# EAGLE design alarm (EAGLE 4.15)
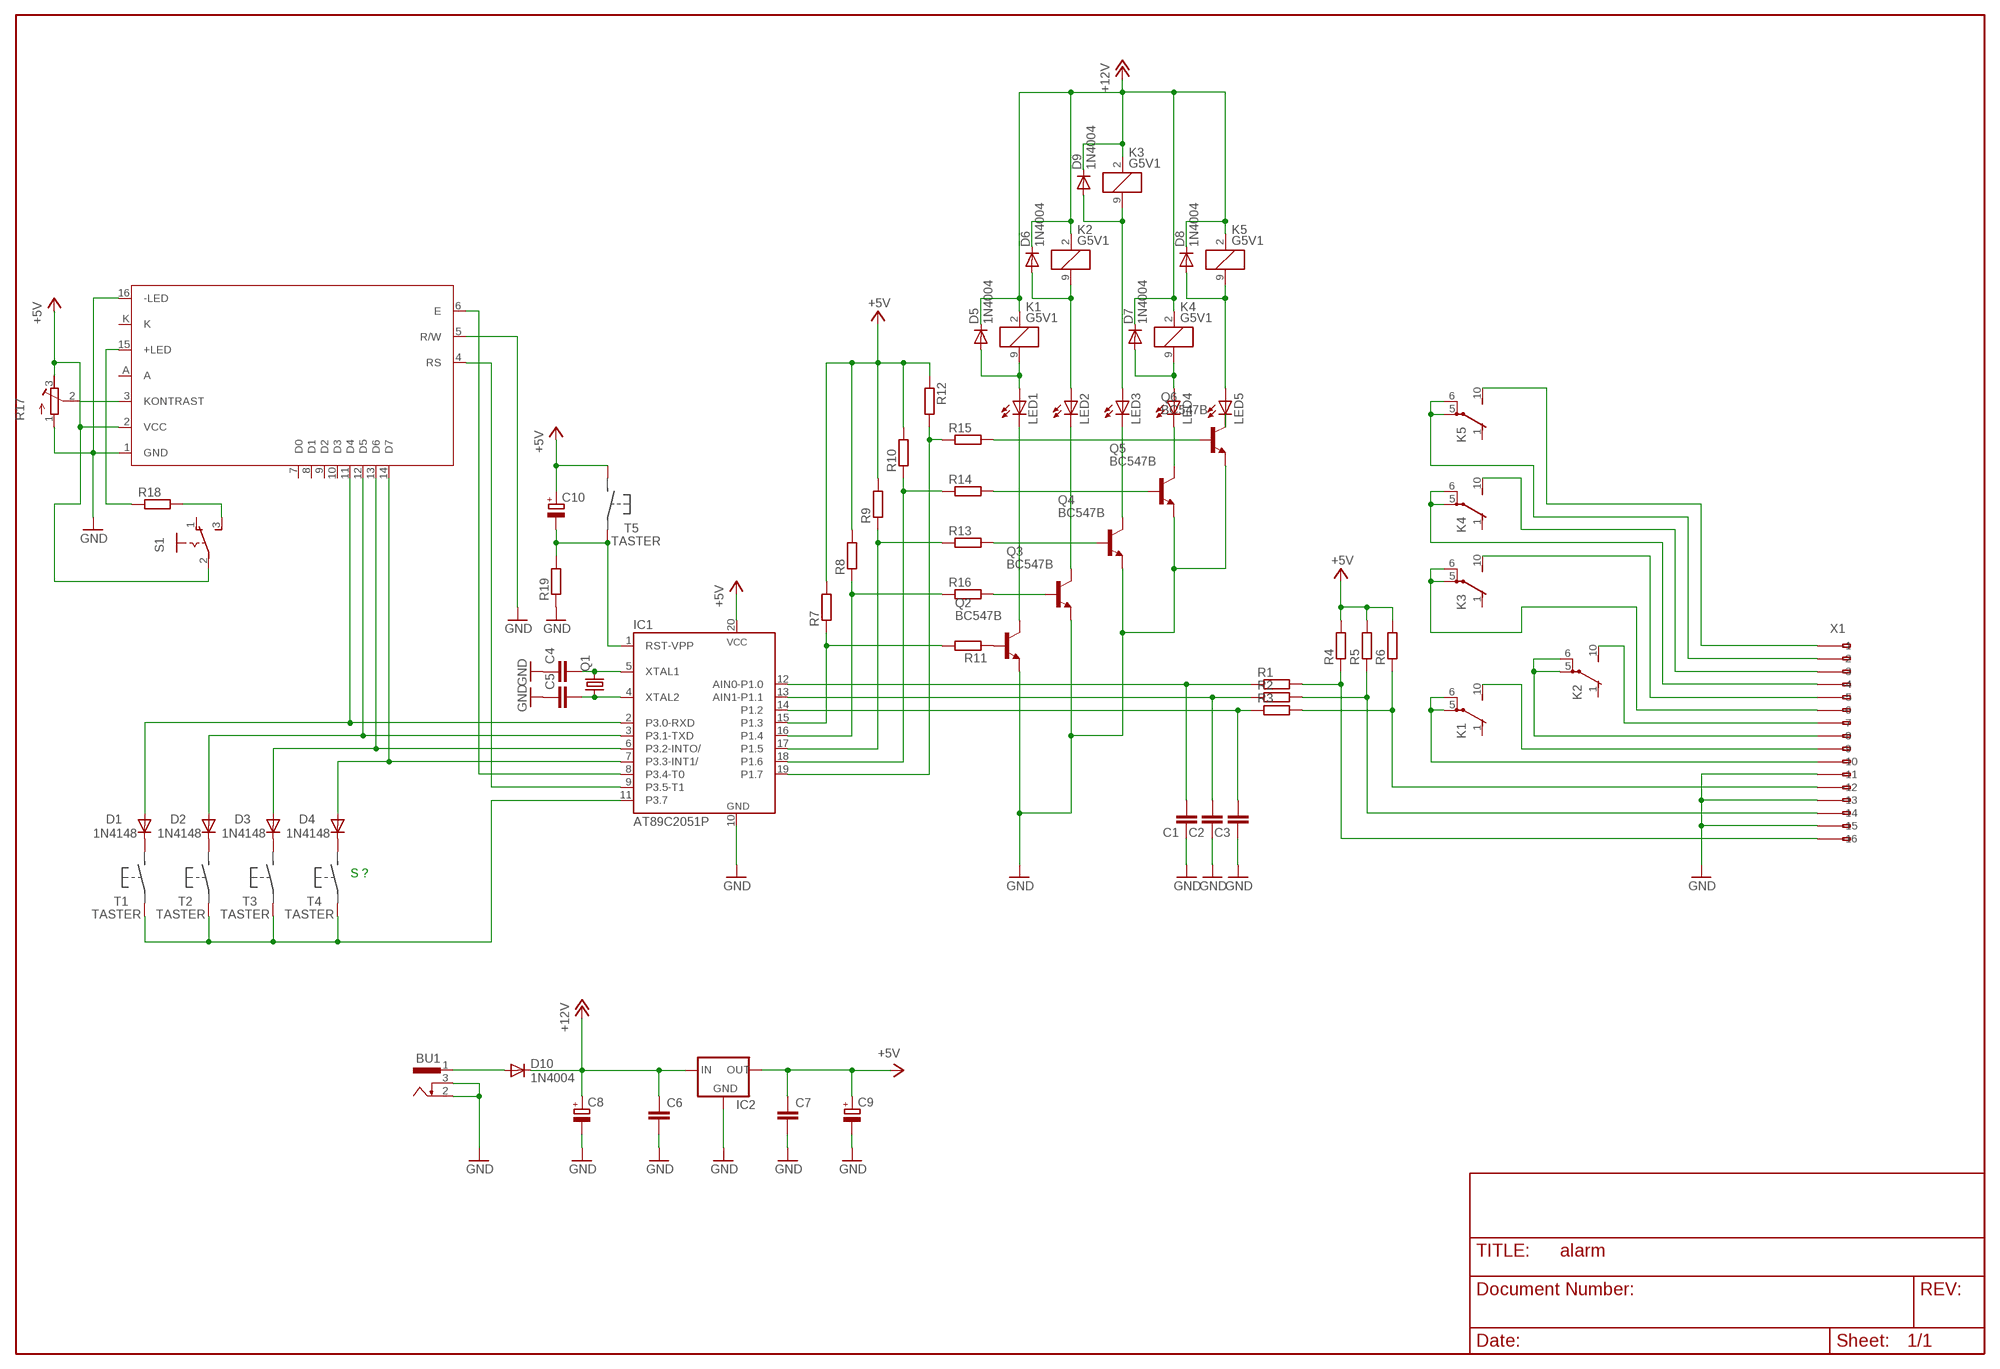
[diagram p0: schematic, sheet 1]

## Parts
BU1  733989-55  [733989-5]
C1  C-EU025-025X050  [C025-025X050]
C2  C-EU025-025X050  [C025-025X050]
C3  C-EU025-025X050  [C025-025X050]
C4  C-EU050-024X044  [C050-024X044]
C5  C-EU050-024X044  [C050-024X044]
C6  C-EU050-025X075  [C050-025X075]
C7  C-EU050-025X075  [C050-025X075]
C8  CPOL-EUE3.5-10  [E3,5-10]
C9  CPOL-EUE2-5  [E2-5]
C10  CPOL-EUE2.5-5  [E2,5-5]
D1  1N4148  [DO35-10]
D2  1N4148  [DO35-10]
D3  1N4148  [DO35-10]
D4  1N4148  [DO35-10]
D5  1N4004  [DO41-10]
D6  1N4004  [DO41-10]
D7  1N4004  [DO41-10]
D8  1N4004  [DO41-10]
D9  1N4004  [DO41-10]
D10  1N4004  [DO41-10]
IC1  AT89C2051P  [DIL20]
IC2  78XXL  [78XXL]
K1  G5V1  [G5V1]
K2  G5V1  [G5V1]
K3  G5V1  [G5V1]
K4  G5V1  [G5V1]
K5  G5V1  [G5V1]
LCD1  LCD-DOT  [LCD-DOT]
LED1  LED5MM  [LED5MM]
LED2  LED5MM  [LED5MM]
LED3  LED5MM  [LED5MM]
LED4  LED5MM  [LED5MM]
LED5  LED5MM  [LED5MM]
Q1  CRYTALHC49U-V  [HC49U-V]
Q2  BC547B  [TO92]
Q3  BC547B  [TO92]
Q4  BC547B  [TO92]
Q5  BC547B  [TO92]
Q6  BC547B  [TO92]
R1  R-EU_0207/10  [0207/10]
R2  R-EU_0207/10  [0207/10]
R3  R-EU_0207/10  [0207/10]
R4  R-EU_0207/10  [0207/10]
R5  R-EU_0207/10  [0207/10]
R6  R-EU_0207/10  [0207/10]
R7  R-EU_0207/10  [0207/10]
R8  R-EU_0207/10  [0207/10]
R9  R-EU_0207/10  [0207/10]
R10  R-EU_0207/10  [0207/10]
R11  R-EU_0207/10  [0207/10]
R12  R-EU_0207/10  [0207/10]
R13  R-EU_0207/10  [0207/10]
R14  R-EU_0207/10  [0207/10]
R15  R-EU_0207/10  [0207/10]
R16  R-EU_0207/10  [0207/10]
R17  R-TRIMM64W  [RTRIM64W]
R18  R-EU_0309/10  [0309/10]
R19  R-EU_0207/10  [0207/10]
S1  255SB  [255SB]
T1  TASTER  [B3F-10XX]
T2  TASTER  [B3F-10XX]
T3  TASTER  [B3F-10XX]
T4  TASTER  [B3F-10XX]
T5  TASTER  [B3F-10XX]
X1  233-216  [233-216]

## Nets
+5V: C7.1 C9.+ C10.+ IC1.20(VCC) IC2.OUT LCD1.2(VCC) R4.2 R5.2 R6.2 R7.2 R8.2 R9.2 R10.2 R12.1 R17.3(A) S1.2(P) T5.1
+12V: C6.1 C8.+ D5.C D6.C D7.C D8.C D9.C D10.C IC2.IN K1.2 K2.2 K3.2 K4.2 K5.2
GND: BU1.2 BU1.3 C1.1 C2.1 C3.1 C4.1 C5.1 C6.2 C7.2 C8.- C9.- IC1.10(GND) IC2.GND LCD1.1(GND) LCD1.5(R/W) LCD1.16(-LED) Q2.1(E) Q3.1(E) Q4.1(E) Q5.1(E) Q6.1(E) R17.1(E) R19.1 X1.A11(-11) X1.A13(-13) X1.A15(-15)
N$1: C1.2 IC1.12(AIN0-P1.0) R1.1
N$2: C2.2 IC1.13(AIN1-P1.1) R2.1
N$3: C3.2 IC1.14(P1.2) R3.1
N$4: R1.2 R4.1 X1.A16(-16)
N$5: R2.2 R5.1 X1.A14(-14)
N$6: R3.2 R6.1 X1.A12(-12)
N$7: D1.A IC1.2(P3.0-RXD) LCD1.11(D4)
N$8: D2.A IC1.3(P3.1-TXD) LCD1.12(D5)
N$9: D3.A IC1.6(P3.2-INTO/) LCD1.13(D6)
N$10: D4.A IC1.7(P3.3-INT1/) LCD1.14(D7)
N$11: IC1.8(P3.4-T0) LCD1.6(E)
N$12: IC1.9(P3.5-T1) LCD1.4(RS)
N$13: C4.2 IC1.5(XTAL1) Q1.2
N$14: C5.2 IC1.4(XTAL2) Q1.1
N$15: IC1.11(P3.7) T1.3 T2.3 T3.3 T4.3
N$16: Q2.2(B) R11.1
N$17: D1.C T1.1
N$18: D2.C T2.1
N$19: D3.C T3.1
N$20: D4.C T4.1
N$21: Q3.2(B) R16.2
N$22: Q4.2(B) R13.2
N$23: Q5.2(B) R14.2
N$24: Q6.2(B) R15.2
N$25: IC1.19(P1.7) R12.2 R15.1
N$26: IC1.18(P1.6) R10.1 R14.1
N$27: IC1.17(P1.5) R9.1 R13.1
N$28: IC1.16(P1.4) R8.1 R16.1
N$29: IC1.15(P1.3) R7.1 R11.2
N$30: BU1.1 D10.A
N$31: C10.- IC1.1(RST-VPP) R19.2 T5.3
N$32: LED2.K(C) Q3.3(C)
N$33: D9.A K3.9 LED3.A
N$34: D5.A K1.9 LED1.A
N$35: D6.A K2.9 LED2.A
N$36: LED3.K(C) Q4.3(C)
N$37: D7.A K4.9 LED4.A
N$38: D8.A K5.9 LED5.A
N$39: LED1.K(C) Q2.3(C)
N$40: LED5.K(C) Q6.3(C)
N$41: LED4.K(C) Q5.3(C)
N$42: LCD1.15(+LED) R18.1
N$43: K1.5(2:P) K1.6(2:P) X1.A10(-10)
N$44: K1.10(2:S) X1.A9(-9)
N$48: K2.5(2:P) K2.6(2:P) X1.A8(-8)
N$49: K2.10(2:S) X1.A7(-7)
N$50: K3.5(2:P) K3.6(2:P) X1.A6(-6)
N$51: K3.10(2:S) X1.A5(-5)
N$52: K4.5(2:P) K4.6(2:P) X1.A4(-4)
N$53: K4.10(2:S) X1.A3(-3)
N$54: K5.5(2:P) K5.6(2:P) X1.A2(-2)
N$55: K5.10(2:S) X1.A1(-1)
N$56: LCD1.3(KONTRAST) R17.2(S)
N$60: R18.2 S1.3(S)
Unconnected: K1.1(2:O) K2.1(2:O) K3.1(2:O) K4.1(2:O) K5.1(2:O) LCD1.7(D0) LCD1.8(D1) LCD1.9(D2) LCD1.10(D3) LCD1.A LCD1.K S1.1(O) X1.B1(B-1) X1.B2(B-2) X1.B3(B-3) X1.B4(B-4) X1.B5(B-5) X1.B6(B-6) X1.B7(B-7) X1.B8(B-8) X1.B9(B-9) X1.B10(B-10) X1.B11(B-11) X1.B12(B-12) X1.B13(B-13) X1.B14(B-14) X1.B15(B-15) X1.B16(B-16)

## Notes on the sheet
- S ?

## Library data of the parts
BU1 = con-conrad:733989-55: FEMALE PRINT CONNECTOR Außen-Ø 4,2 mm, Innen 1.1 mm FUK HING Industries, distributor Conrad
C1-C7 = rcl:C-EU: CAPACITOR, European symbol
C8-C10 = rcl:CPOL-EU: POLARIZED CAPACITOR, European symbol
D1-D4 = diode:1N4148: DIODE
D5-D10 = diode:1N4004: DIODE
IC1 = atmel:AT89C2051: 80C31 MICROCONTROLLER 2 Kbytes FLASH 2.7 V
IC2 = v-reg:78XXL: VOLTAGE REGULATOR
K1-K5 = relay:G5V1: RELAY 1 x switch, 0.5 A/125 V AC, 1 A/24 V DC , Omron
LCD1 = display-lcd:LCD-DOT
LED1-LED5 = led:LED: LED
Q1 = crystal:CRYTAL: CRYSTAL
Q2-Q6 = transistor-npn:BC547*: NPN Transistor
R1-R16 R18 R19 = rcl:R-EU_: RESISTOR, European symbol
R17 = rcl:R-TRIMM: Trimm resistor
S1 = switch:255SB: SLIDING SWITCH distributor Buerklin, 11G810
T1-T5 = switch-omron:TASTER: Digi-Taster
X1 = con-wago255:233-216: WAGO

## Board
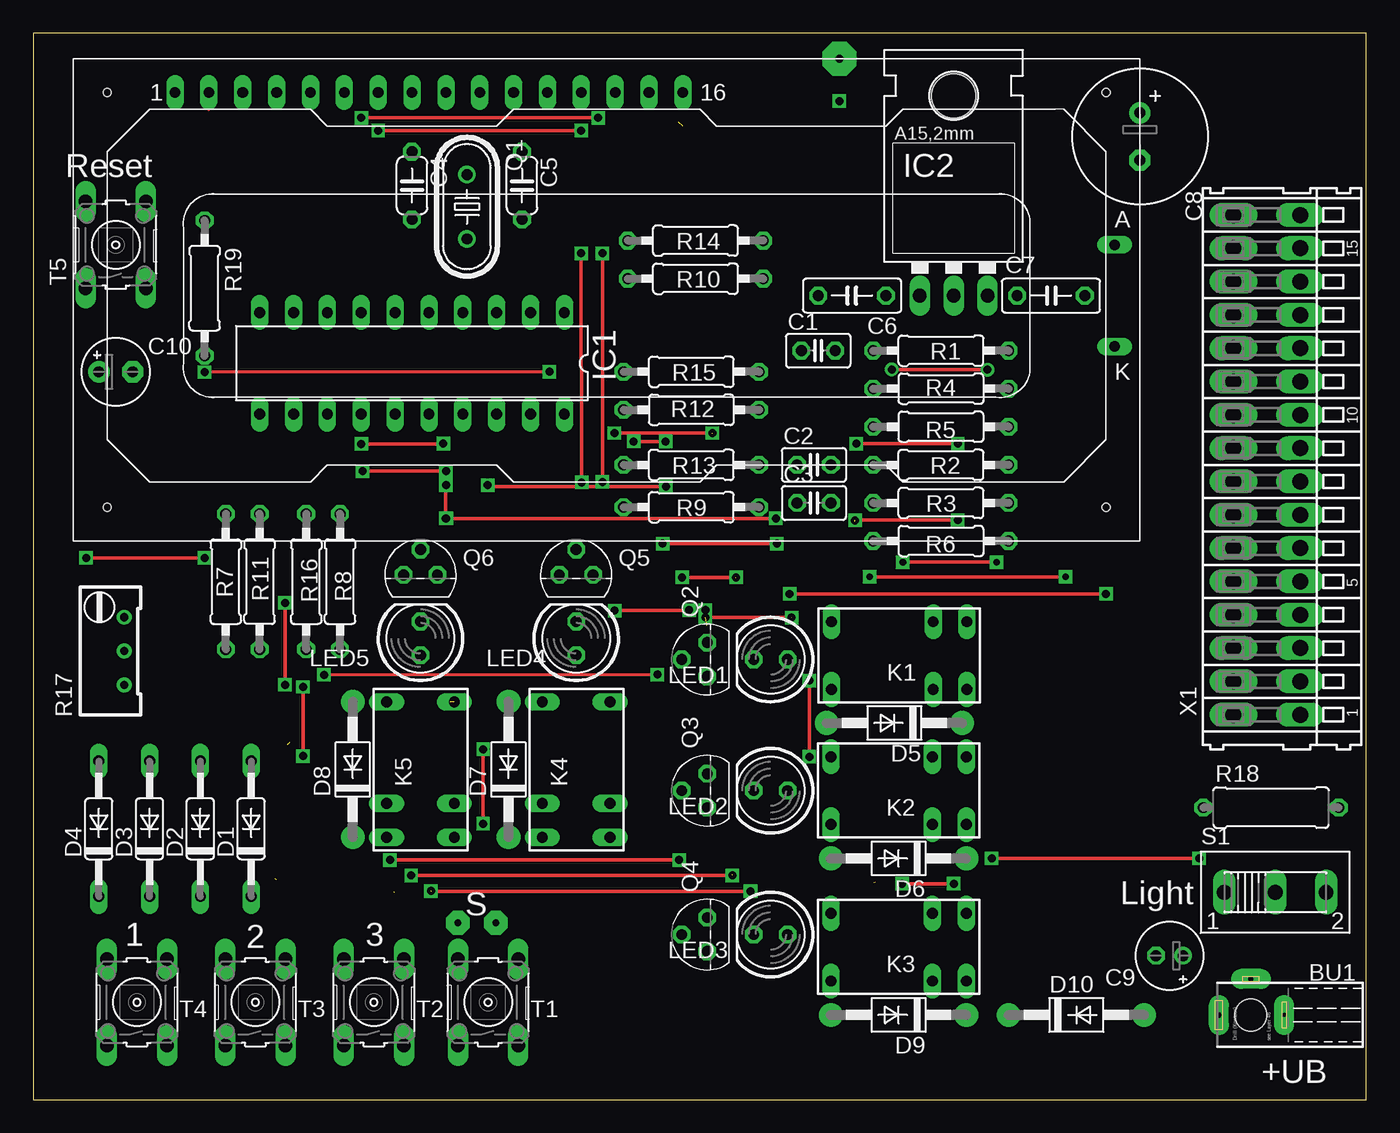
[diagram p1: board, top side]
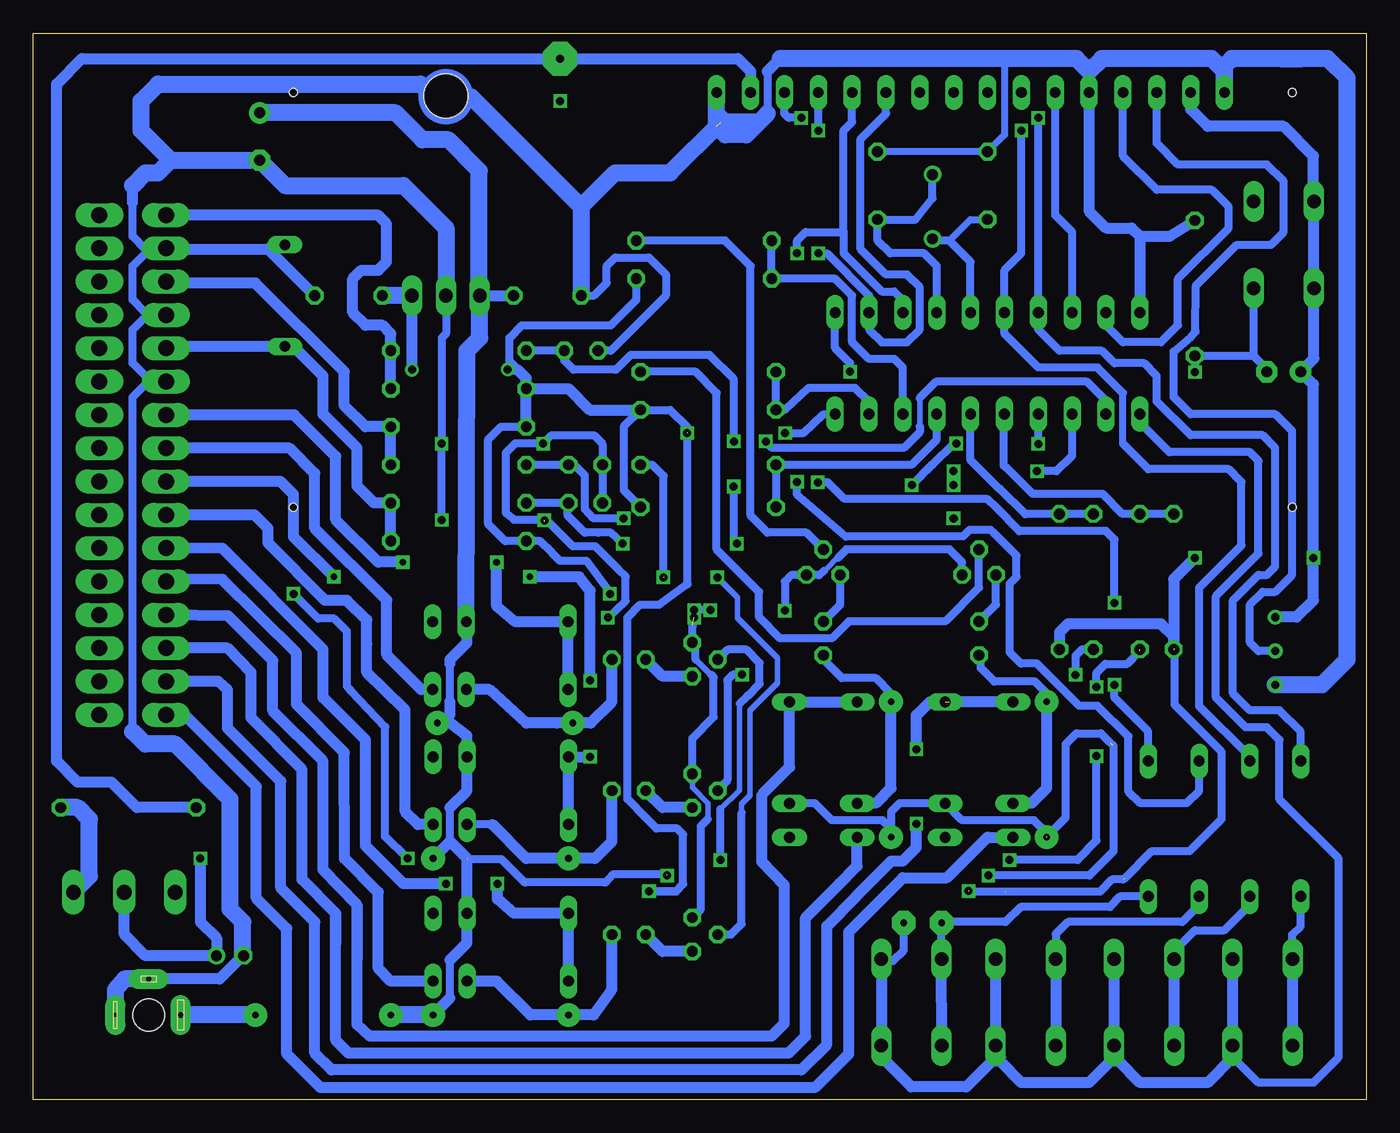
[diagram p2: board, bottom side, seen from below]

Size 100 x 80 mm. Coordinates in mm from the lower left corner, seen from the top.
Outline: 0,0 100,0 100,80 0,80 0,0
Copper layers (1*16): Top 0.035mm / dielectric 1.5mm / Bottom 0.035mm
Design rules "default": minimum track width 10mil, minimum drill 24mil, track to track 8mil, track to pad 8mil, pad to pad 8mil, via to via 8mil, smd to smd 8mil, copper to edge 40mil, drill to drill 8mil, minimum pad ring 10mil, minimum via ring 8mil, stop-mask expansion 4mil, vias tented up to drill 0mil, thermal gap 10mil

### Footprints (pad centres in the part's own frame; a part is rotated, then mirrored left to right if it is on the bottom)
733989-5 = drill 0.4 pad 1.5 long: 1 0,5.82; 3 2.7,3.42 | drill 0.3 pad 1.5 long: 2 0,0.92 | hole 2.4: 0,3.42
C025-025X050 = drill 0.813 octagon: 1 -1.27,0; 2 1.27,0
C050-024X044 = drill 0.813 octagon: 1 -2.54,0; 2 2.54,0
C050-025X075 = drill 0.813 octagon: 1 -2.54,0; 2 2.54,0
E3,5-10 = drill 0.813 pad 1.6 round: + -1.778,0 | drill 0.813 pad 1.6 octagon: - 1.778,0
E2-5 = drill 0.813 pad 1.27 round: + -1.016,0 | drill 0.813 pad 1.27 octagon: - 1.016,0
E2,5-5 = drill 0.813 pad 1.6 round: + -1.27,0 | drill 0.813 pad 1.6 octagon: - 1.27,0
DO35-10 = drill 0.813 long: A 5.08,0; C -5.08,0
DO41-10 = drill 0.5 pad 1.778 round: A 5.08,0; C -5.08,0
DIL20 = drill 0.813 long: 1 -11.43,-3.81; 2 -8.89,-3.81; 3 -6.35,-3.81; 4 -3.81,-3.81; 5 -1.27,-3.81; 6 1.27,-3.81; 7 3.81,-3.81; 8 6.35,-3.81; 9 8.89,-3.81; 10 11.43,-3.81; 11 11.43,3.81; 12 8.89,3.81; 13 6.35,3.81; 14 3.81,3.81; 15 1.27,3.81; 16 -1.27,3.81; 17 -3.81,3.81; 18 -6.35,3.81; 19 -8.89,3.81; 20 -11.43,3.81
78XXL = drill 1.016 long: GND 0,-3.81; IN -2.54,-3.81; OUT 2.54,-3.81 | hole 3.302: 0,11.176
G5V1 = drill 0.813 long: 1 -5.08,-2.54; 2 -2.54,-2.54; 5 5.08,-2.54; 6 5.08,2.54; 9 -2.54,2.54; 10 -5.08,2.54
LCD-DOT = drill 0.8 long: 1 -33.02,15.24; 2 -30.48,15.24; 3 -27.94,15.24; 4 -25.4,15.24; 5 -22.86,15.24; 6 -20.32,15.24; 7 -17.78,15.24; 8 -15.24,15.24; 9 -12.7,15.24; 10 -10.16,15.24; 11 -7.62,15.24; 12 -5.08,15.24; 13 -2.54,15.24; 14 0,15.24; 15 2.54,15.24; 16 5.08,15.24; A 37.465,3.81; K 37.465,-3.81 | hole 0.6: -38.1,15.24; 36.83,15.24; -38.1,-15.875; 36.83,-15.875
LED5MM = drill 0.813 octagon: A -1.27,0; K 1.27,0
HC49U-V = drill 0.813 round: 1 -2.413,0; 2 2.413,0
TO92 = drill 0.813 octagon: 1 1.27,0; 2 0,1.905; 3 -1.27,0
0207/10 = drill 0.813 octagon: 1 -5.08,0; 2 5.08,0
RTRIM64W = drill 0.61 round: 1 1.27,-2.54; 2 1.27,0; 3 1.27,2.54
0309/10 = drill 0.813 octagon: 1 -5.08,0; 2 5.08,0
255SB = drill 1.118 long: 1 -3.81,0; 2 0,0; 3 3.81,0
B3F-10XX = drill 1.016 long: 1 -3.251,2.261; 2 3.251,2.261; 3 -3.251,-2.261; 4 3.251,-2.261
233-216 = drill 1.2 long: A1 -18.75,2.5; A2 -16.25,2.5; A3 -13.75,2.5; A4 -11.25,2.5; A5 -8.75,2.5; A6 -6.25,2.5; A7 -3.75,2.5; A8 -1.25,2.5; A9 1.25,2.5; A10 3.75,2.5; A11 6.25,2.5; A12 8.75,2.5; A13 11.25,2.5; A14 13.75,2.5; A15 16.25,2.5; A16 18.75,2.5; B1 -18.75,-2.5; B2 -16.25,-2.5; B3 -13.75,-2.5; B4 -11.25,-2.5; B5 -8.75,-2.5; B6 -6.25,-2.5; B7 -3.75,-2.5; B8 -1.25,-2.5; B9 1.25,-2.5; B10 3.75,-2.5; B11 6.25,-2.5; B12 8.75,-2.5; B13 11.25,-2.5; B14 13.75,-2.5; B15 16.25,-2.5; B16 18.75,-2.5

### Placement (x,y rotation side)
BU1  94.77,6.34 90 top
C1  58.89,56.19 0 top
C2  58.57,47.62 0 top
C3  58.57,44.76 0 top
C4  28.41,68.57 270 top
C5  36.66,68.57 270 top
C6  61.43,60.32 180 top
C7  76.35,60.32 0 top
C8  83.02,72.26 270 top
C9  85.24,10.79 180 top
C10  6.18,54.61 0 top
D1  16.34,20.31 90 top
D2  12.54,20.31 90 top
D3  8.73,20.31 90 top
D4  4.92,20.31 90 top
D5  64.61,28.25 180 top
D6  64.92,18.09 180 top
D7  35.65,24.76 90 top
D8  23.96,24.76 90 top
D9  64.92,6.34 180 top
D10  78.26,6.34 0 top
IC1  28.41,55.24 180 top
IC2  69.05,64.13 0 top
K1  64.97,33.31 180 top
K2  64.92,23.17 180 top
K3  64.92,11.43 180 top
K4  40.73,24.76 90 top
K5  29.04,24.76 90 top
LCD1  43.65,60.32 0 top
LED1  55.32,33.02 180 top
LED2  55.32,23.17 180 top
LED3  55.32,12.38 180 top
LED4  40.73,34.6 90 top
LED5  29.04,34.6 90 top
Q1  32.54,66.99 270 top
Q2  50.56,33.02 90 top
Q3  50.56,23.17 90 top
Q4  50.56,12.38 90 top
Q5  40.73,39.37 0 top
Q6  29.04,39.37 0 top
R1  68.1,56.19 0 top
R2  68.1,47.62 0 top
R3  68.1,44.76 0 top
R4  68.1,53.34 180 top
R5  68.1,50.48 180 top
R6  68.1,41.91 180 top
R7  14.44,38.86 270 top
R8  23.01,38.86 270 top
R9  49.37,44.45 0 top
R10  49.68,61.59 0 top
R11  16.98,38.86 90 top
R12  49.37,51.75 180 top
R13  49.37,47.62 0 top
R14  49.68,64.45 0 top
R15  49.37,54.61 0 top
R16  20.47,38.86 270 top
R17  5.55,33.65 0 top
R18  92.86,21.9 0 top
R19  12.85,60.88 270 top
S1  93.18,15.55 0 top
T1  34.12,7.3 90 top
T2  25.55,7.3 90 top
T3  16.66,7.3 90 top
T4  7.77,7.3 90 top
T5  6.18,64.13 90 top
X1  92.55,47.62 90 top

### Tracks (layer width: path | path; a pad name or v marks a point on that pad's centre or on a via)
+5V  (via drill 0.6, 0.6 pad 1.02)  (6 unrouted)
  Top 0.254: v64.4,54.78 v71.6,54.75 | v3.96,40.64 v12.85,40.64 | v50.95,50.01 v43.6,50.01 | v71.91,18.09 v87.47,18.09 | C7.1 74.13,60.32 | LCD1.2 13.17,74.29 | R10.2 55.08,61.59 | v80.48,37.94 v56.74,37.94 | 29.84,15.63 v53.8,15.63
  Bottom 0.61: R5.2 64.92,50.48 65.88,49.53 65.88,43.18 64.61,41.91 R6.2 63.02,41.94 | 63.02,54.13 64.29,55.4 64.29,57.15 63.34,58.1 56.67,58.1 54.76,60 R10.2 | R9.2 55.71,45.72 55.71,50.48 R12.1 52.22,51.75 50.95,50.48 v50.95,50.01 | IC1.20 40.72,51.43 42.2,50.02 43.16,50.02 v43.6,50.01 | v71.91,18.09 73.61,19.73 73.6,27.96 76.16,30.65 | 76.16,30.65 76.21,30.75 | 76.16,30.65 76.47,31.01 76.47,35.12 77.43,36.09 78.63,36.09 v80.48,37.94 | 63.02,41.94 63.03,41.96 | 63.02,41.94 62.98,41.91 61.96,41.91 61.1,41.04 61.1,41.02 60.49,40.41 60.49,40.46 60.44,40.41 58.51,40.41 56.76,38.1 v56.74,37.94 | 50.91,50.01 50.91,38.68 53.02,37.13 54.47,37.13 55.44,36.16 55.44,22.55 53.99,21.1 53.99,21.08 53.25,20.34 51.7,20.34 51.24,19.88 51.24,16.18 | 51.24,16.18 51.77,15.62 v53.82,15.62 | 27.09,15.59 29.43,15.59 v29.82,15.64 | 27.01,15.59 19.98,15.59 19.06,16.5 18.22,16.5 | 14.36,33.83 14.36,29.61 10.83,26.08 10.83,21.05 13.25,18.64 16.07,18.64 18.1,16.61 | 51.24,16.18 51.79,15.63 v53.8,15.63
  Bottom 0.813: LCD1.2 13.17,74.29 11.9,73.02 6.18,73.02 3.96,70.8 3.96,67.62 3.92,67.58 T5.1 3.92,55.6 C10.+ 3.96,53.65 v3.96,40.64 3.96,37.46 5.23,36.19 R17.3 | R5.2 R4.2 | IC2.OUT 71.59,56.51 v71.6,54.75 | v64.4,54.78 63.65,54.76 63.02,54.13 R4.2 | S1.2 93.18,12.38 91.59,10.79 C9.+ 86.26,12.12 87.47,13.33 v87.47,18.09 | R12.1 58.25,51.75 59.84,53.34 R4.2 | R8.2 23.01,35.05 22.38,35.68 15.39,35.68 14.44,34.73 R7.2 14.44,39.05 v12.85,40.64
  Bottom 1.27: IC2.OUT C7.1
+12V  (via drill 0.6)  (5 unrouted)
  Top 0.254: K4.2 43.9,22.22 | D6.C 70.32,18.41 | v28.35,16.81 v52.44,16.81 52.59,16.71
  Bottom 0.61: 68.73,19.36 68.73,21.9 | 68.73,7.62 68.73,10.47 | 68.73,29.84 68.73,32.7 | D8.C 23.96,20 24.92,20.95 30.31,20.95 K5.2 35.01,22.22 35.65,21.58 35.65,20.31 | 35.65,20.31 D7.C | K4.2 41.36,22.22 40.09,20.95 36.28,20.95 35.65,20.31 | 63.08,16.28 57.09,16.28 56.53,16.89 52.44,16.89 | 67.45,18.03 64.88,18.03 63.18,16.33 | 19.04,26.61 18.94,26.51 18.94,18.64 20.77,16.81 v28.35,16.81 | 23.94,19.78 23.94,19.76 22.54,21.15 22.54,26.66 21.73,27.48 19.9,27.48 19.21,26.79
  Bottom 0.813: D6.C 68.73,19.36 67.46,18.09 K3.2 67.46,11.74 68.73,10.47 | 68.73,21.9 67.46,23.17 K2.2 67.46,27.3 68.73,28.25 D5.C 69.05,28.57 68.73,28.89 68.73,29.84 | 68.73,7.62 D9.C | 68.73,32.7 68.73,33.02 67.46,34.29 K1.2 | 66.54,60.32 IC2.IN C6.1
  Bottom 1.27: K1.2 67.46,56.19 66.51,57.15 IC2.IN | D9.C D10.C | C8.+ 72.83,74.04 70.8,72 68.86,72 66.54,69.69 66.54,60.32
GND  (via drill 0.6, 0.6 pad 1.02)  (6 unrouted)
  Top 0.254: C9.- 84.29,10.79 | v69.37,49.21 v61.75,49.21 | 61.66,43.48 v69.36,43.48 | v43.61,36.69 49.16,36.69 v49.2,36.72 | v50.42,36.72 v50.42,36.15 56.6,36.15 v56.9,36.16
  Bottom 0.254: C9.- 84.29,10.79 | 27.14,78.1 27.14,77.78 | v56.9,36.16 55.69,37.36
  Bottom 0.406: 39.61,40.66 39.66,40.66 40.5,39.82 40.68,39.67 | 41.03,39.34 40.91,39.47 41.09,39.34 | 42.05,39.34 42.02,39.37 Q5.1 | Q3.1 50.56,23.41 49.37,22.22 49.37,21.08 49.39,21.05 | 49.14,31.87 49.16,31.87 50.3,33.02
  Bottom 0.508: 27.14,77.78 27.14,72.38 C4.1 C5.1
  Bottom 0.61: 44.92,77.15 44.92,73.97 | 92.55,67.3 92.55,64.77 91.59,63.81 90,63.81 | 90,63.81 90.05,63.85 X1.A15 | 90,63.81 91.28,63.81 92.55,62.54 92.55,60 91.59,59.05 90.32,59.05 90.14,58.87 X1.A13 91.45,58.87 92.55,57.78 92.55,55.24 91.28,53.97 | X1.A11 90.05,53.93 90,53.97 91.28,53.97 | 91.28,53.97 92.55,52.7 92.55,27.62 | 91.34,9.04 91.35,8.96 BU1.3 | C9.- 84.23,10.85 | C6.2 57.94,60.32 56.98,61.27 56.98,62.54 56.35,63.18 53.81,63.18 52.54,61.91 52.54,60.32 56.67,56.19 C1.1 | C3.1 C2.1 57.3,49.21 57.94,49.84 61.11,49.84 61.73,49.22 | v61.75,49.21 61.73,49.22 | v69.37,49.21 69.37,57.15 69.05,57.46 IC2.GND | Q6.1 30.31,40.33 31.25,41.27 39,41.27 39.61,40.66 | 40.68,39.67 41.03,39.34 | 41.09,39.34 42.05,39.34 43.14,39.34 43.61,38.87 v43.61,36.69 | Q4.1 50.55,13.65 49.92,14.27 49.92,20.52 49.39,21.05 | Q3.1 50.56,27.1 48.96,28.7 48.96,31.69 49.14,31.87 | 50.3,33.02 50.3,33.98 50.53,34.29 Q2.1 50.53,35.55 | 61.73,49.22 63.84,49.22 64.55,48.51 64.55,44.01 63.95,43.51 61.51,43.51 | v69.36,43.48 69.36,49.22 | v49.2,36.72 v50.42,36.72 | 61.65,43.38 61.39,43.38 59.52,41.51 57.84,41.51 56.08,39.76 56.08,39.75 55.56,39.23 55.56,37.41 56.88,36.15
  Bottom 0.813: C7.2 82.39,63.81 89.37,63.81 89.41,63.85 X1.A15 | 16.98,64.77 IC1.10 | 16.98,64.77 17.61,65.4 19.52,65.4 20.79,66.67 LCD1.5 20.79,77.15 | R19.1 14.73,64.77 16.98,64.77 | 43.97,78.1 44.92,77.15 | 92.55,67.3 92.55,68.57 | BU1.3 86.03,9.04 84.29,10.79 84.23,10.85
  Bottom 1.27: 44.92,73.97 46.51,72.38 48.09,72.38 48.73,73.02 LCD1.16 | 43.97,78.1 27.14,78.1 21.74,78.1 20.79,77.15 19.84,78.1 11.58,78.1 10.63,77.15 LCD1.1 10.63,77.55 10.08,78.1 6.44,78.1 | R17.1 3.33,31.11 1.42,33.02 1.42,76.65 2.81,78.04 2.84,78.04 2.91,78.1 6.44,78.1 | 4.83,78.1 4.76,78.12 4.79,78.1 6.44,78.1 | 89.69,70.48 90.64,69.53 91.59,69.53 92.55,68.57 | 92.55,27.62 91.59,26.66 89.37,26.66 85.24,22.54 85.24,14.28 84.29,13.33 84.29,10.79 | BU1.2 93.85,8.22 93.15,9.04 91.34,9.04 | 89.69,70.48 C8.- | IC2.GND 69.05,65.4 72.22,68.57 81.11,68.57 C8.- | C8.- | 89.69,70.48 91.91,72.7 91.91,74.92 90.64,76.19 70.95,76.19 70,75.24 67.14,75.24 58.89,66.99 | 58.89,66.99 C6.2 | 58.89,66.99 56.35,69.53 52.22,69.53 48.41,73.34 | 48.41,73.34 48.41,73.66 | 48.41,73.34 47.78,72.7 46.82,72.7
  other vias: 61.66,43.45
N$1  (via drill 0.6)
  Top 0.254: C1.2 60.16,56.51 | v45.05,49.37 v47.44,49.37
  Bottom 0.406: 33.49,50.52 33.49,52.6 33.52,52.62
  Bottom 0.61: R1.1 C1.2 60.16,55.44 59.47,54.76 56.3,54.76 55.18,55.88 49.26,55.88 47.44,54.05 v47.44,49.37 | v45.05,49.37 44.56,48.89 34.68,48.89 33.49,50.08 33.49,50.52 | 33.52,52.62 32.27,53.87 20.94,53.87 19.52,52.45 IC1.12 19.54,51.41
N$2  (via drill 0.6 pad 1.02)
  Top 0.254: v55.71,43.61 v30.97,43.61 30.94,43.57 | v24.7,47.15 v30.96,47.15 | v30.94,43.61 30.94,46.07 v30.96,46.1
  Bottom 0.254: 30.94,47.15 v30.96,47.15 v30.96,46.1
  Bottom 0.61: R2.1 C2.2 59.4,47.62 58.61,46.83 58.61,44.29 57.95,43.61 v55.71,43.61 | IC1.13 22.06,48.32 23.23,47.15 v24.7,47.15 | v30.94,43.61 v30.97,43.61
N$3  (via drill 0.6 pad 1.02)
  Top 0.254: C3.2 60.16,45.08 | v24.6,49.2 30.73,49.2 v30.76,49.22 | v47.22,41.7 v55.79,41.7 | v47.46,45.99 34.1,45.99 v34.1,46.1
  Bottom 0.254: 32.53,47.63 32.56,47.63 | 32.53,47.63
  Bottom 0.61: R3.1 C3.2 59.91,44.83 59.91,43.81 58.64,42.54 57.62,42.54 56.68,42.53 v55.79,41.7 | v24.6,49.2 IC1.14 | v30.76,49.22 30.94,49.22 32.53,47.63 32.91,47.25 | v47.22,41.7 47.46,41.94 v47.46,45.99 | 32.56,47.63 v34.1,46.1
N$4
  Bottom 0.813: R4.1 R1.2 73.18,57.46 73.81,58.1 75.08,58.1 76.03,59.05 76.03,61.59 75.4,62.23 74.13,62.23 73.5,62.86 73.5,65.72 74.13,66.35 89.37,66.35 89.09,66.31 X1.A16
N$5
  Bottom 0.813: R2.2 R5.1 75.08,50.48 76.67,52.07 76.67,54.61 83.34,61.27 89.05,61.27 89.15,61.37 X1.A14
N$6
  Bottom 0.813: R6.1 R3.2 74.45,44.76 75.72,46.03 75.72,48.89 78.26,51.43 78.26,54.29 80.48,56.51 89.37,56.51 89.41,56.47 X1.A12
N$7  (via drill 0.6)
  Top 0.254: v41.13,46.31 v41.11,63.5 | v18.88,31.11 v18.88,37.27
  Bottom 0.61: LCD1.11 36.03,73.97 37.94,72.07 37.94,63.81 36.03,61.91 34.44,61.91 33.49,60.96 33.49,57.78 34.44,56.83 36.35,56.83 37.3,57.78 IC1.2 37.3,60.32 40.48,63.5 v41.11,63.5 | v41.13,46.31 40.39,46.31 39.14,45.07 28.41,45.05 27.72,44.39 26.02,42.64 19.52,42.67 18.88,42.03 v18.88,37.27 | v18.88,31.11 18.88,30.16 16.34,27.62 D1.A
N$8  (via drill 0.6)
  Top 0.254: v42.7,46.35 v42.7,63.5
  Bottom 0.61: IC1.3 34.76,60 35.39,60.64 36.35,60.64 39.2,63.5 39.2,65.08 | 39.2,65.08 39.2,72.7 38.57,73.34 LCD1.12 | 39.2,65.08 42.06,65.08 42.7,64.45 v42.7,63.5 | D2.A 12.54,23.17 13.49,22.22 16.94,22.22 17.84,23.1 17.84,27.26 20.15,29.52 20.15,29.54 21.53,29.54 24.7,32.71 25.89,32.71 26.73,33.55 26.73,38.71 26.23,39.21 26.23,40.81 27.88,42.46 27.9,42.46 28.18,42.74 29.76,42.74 30.25,42.25 39.06,42.23 42.7,45.37 v42.7,46.35
N$9  (via drill 0.6)
  Top 0.254: v25.87,72.7 v41.11,72.7
  Bottom 0.508: 18.25,49.21 18.25,53.02
  Bottom 0.61: D3.A 8.73,25.74 8.79,25.8 12.54,29.51 12.54,38.41 9.36,41.59 9.36,46.35 10.31,47.3 16.34,47.3 18.25,49.21 | 18.25,53.02 20.15,54.92 24.6,54.92 27.14,57.46 IC1.6 27.14,62.23 25.87,63.5 v25.87,72.7 | v41.11,72.7 LCD1.13
N$10  (via drill 0.6)
  Top 0.254: v24.6,73.66 v42.38,73.66
  Bottom 0.61: D4.A 4.92,27.62 6.5,29.2 8.73,29.2 10,30.47 10,37.46 8.09,39.37 7.46,39.37 6.82,40 6.82,48.89 7.77,49.84 13.17,49.84 15.71,52.38 15.71,54.29 16.66,55.24 18.88,55.24 19.84,56.19 23.01,56.19 24.6,57.78 IC1.7 v24.6,73.66 | v42.38,73.66 43.33,73.66 43.65,73.97 LCD1.14
N$11
  Bottom 0.61: IC1.8 22.06,65.08 23.33,66.35 LCD1.6
N$12
  Bottom 0.61: IC1.9 19.52,58.1 18.25,56.83 15.39,56.83 14.12,58.1 14.12,61.59 10.31,65.4 10.31,66.99 11.58,68.26 15.71,68.26 18.25,70.8 LCD1.4
N$13
  Bottom 0.508: C4.2 29.68,66.03 31.27,64.45
  Bottom 0.61: IC1.5 29.68,62.86 31.27,64.45 32.54,64.45 Q1.2
N$14
  Bottom 0.61: IC1.4 32.22,62.54 33.17,63.5 35.71,63.5 36.66,64.45 C5.2 33.81,66.03 32.54,67.62 Q1.1
N$15
  Bottom 0.254: T3.3 19.52,3.17 19.2,2.85 | 27.46,2.85 27.14,3.17 T2.3 | T1.3 36.03,4.44 36.35,4.44
  Bottom 0.61: IC1.11 16.98,50.8 14.76,48.57 8.73,48.57 8.09,47.94 8.09,40.95 11.27,37.78 11.27,30.16 9.04,27.93 7.46,27.93 6.5,26.98 6.5,22.54 2.06,18.09 2.06,3.17 3.96,1.27 8.09,1.27 10,3.17 10.03,3.17
  Bottom 0.813: T4.3 10.03,3.17 10.03,3.13 11.9,1.27 16.98,1.27 18.57,2.85 19.2,2.85 20.79,1.27 25.87,1.27 27.46,2.85 28.09,2.85 30,0.95 34.12,0.95 36.35,3.17 36.35,4.44 36.35,10.47
N$16  (via drill 0.6)  (1 unrouted)
  Top 0.254: v20.23,25.76 v20.23,30.96 | v26.76,17.98 v48.45,17.98
  Bottom 0.406: 47.02,29.71 47.02,23.18 48.45,21.79
  Bottom 0.61: 16.98,33.65 17.93,32.7 19.56,32.7 20.23,32.02 v20.23,30.96 | v26.76,17.98 21.65,17.98 20.23,19.43 v20.23,25.76 | Q2.2 47.9,33.76 46.51,33.76 45.5,32.76 45.5,31.19 46.39,30.3 46.43,30.3 47.02,29.71 | v48.45,17.98 48.45,21.79
N$17
  Bottom 0.61: 31.9,10.47 31.9,13.33 27.06,13.33 25.92,14.45 19.21,14.45 18.48,15.24 D1.C
  Bottom 0.813: 31.9,10.47 T1.1
N$18
  Bottom 0.61: 23.29,10.43 23.29,12.42 22.38,13.33 13.81,13.33 12.54,14.6 D2.C
  Bottom 0.813: T2.1 23.29,10.43 23.33,10.47
N$19
  Bottom 0.61: 14.4,10.43 14.4,11.15 12.85,12.7 10.63,12.7 8.73,14.6 D3.C
  Bottom 0.813: T3.1 14.4,10.43 14.44,10.47
N$20
  Bottom 0.61: 5.55,10.47 5.55,12.38 4.92,13.01 D4.C
  Bottom 0.813: T4.1 5.51,10.43 5.55,10.47
N$21  (via drill 0.6)
  Top 0.254: v21.81,31.87 v46.82,31.88
  Bottom 0.61: 20.47,33.71 R16.2 20.59,33.78 20.61,33.75 21.35,33.75 21.81,33.29 v21.81,31.87 | v46.82,31.88 47.5,31.88 47.94,31.44 47.93,31.48 47.93,23.96 48.67,23.17 | 48.67,23.17 48.7,23.13 | 48.67,23.17 Q3.2
N$22  (via drill 0.6)  (1 unrouted)
  Top 0.254: v48.68,39.17 52.69,39.17 52.73,39.14
  Bottom 0.406: 46.86,21.52 46.86,22.2 46.24,22.83 46.24,29.2 44.18,31.25 44.18,33.13 47.17,36.11 47.17,37.66 v48.68,39.17
  Bottom 0.61: R13.2 53.56,47.62 52.72,46.78 52.72,39.16 | Q4.2 47.65,12.38 46.86,13.17 46.86,21.52
N$23
  Bottom 0.61: R14.2 48.09,64.45 46.19,62.54 46.19,43.81 44.92,42.54 42,42.54 Q5.2
N$24
  Bottom 0.61: R15.2 50.32,54.61 48.73,53.02 48.73,41.27 45.55,38.1 45.55,36.19 43.97,34.6 40.09,34.6 38.82,35.87 31.58,35.87 29.04,38.41 Q6.2
N$25
  Bottom 0.61: R15.1 R12.2 43.56,51.77 41.83,53.4 38.34,53.4 37.3,52.38 IC1.19
N$26
  Bottom 0.61: R14.1 R10.1 39.84,61.59 38.57,60.32 38.57,56.83 37.3,55.56 35.39,55.56 34.76,54.92 IC1.18
N$27
  Bottom 0.61: R9.1 R13.1 34.12,47.62 32.22,49.53 IC1.17
N$28
  Bottom 0.61: R8.1 23.13,43.94 | R16.1 R8.1 | R8.1 25.58,43.92 27.47,45.82 27.55,45.84 29.68,47.98 29.68,51.28 29.73,51.33 29.68,51.38 IC1.16
N$29
  Bottom 0.61: R7.1 R11.2 18.27,43.94 19.77,45.44 25.01,45.44 27.04,47.44 27.19,47.54 27.16,51.43 27.14,51.46 IC1.15
N$30
  Bottom 1.27: D10.A BU1.1
N$31  (via drill 0.6)
  Top 0.254: v12.85,54.58 v38.72,54.61
  Bottom 0.61: v12.85,54.58 R19.2 8.45,55.8 | v38.72,54.61 38.72,55.27 39.84,56.38 IC1.1 | 8.01,55.37 8.45,55.8 | 8.01,55.37 | 8.45,55.8 T5.3 | C10.- 7.35,54.71 8.01,55.37 | 8.45,55.8 8.37,55.8
N$32
  Bottom 0.813: Q3.3 52.78,21.9 LED2.K
N$33
  Bottom 0.813: K3.9 65.24,8.89 62.7,6.34 D9.A 57.94,6.34 56.59,8.25 LED3.A
N$34
  Bottom 0.254: D5.A 60.72,28.57 60.72,28.25
  Bottom 0.813: K1.9 65.79,30.77 63.02,28.25 60.72,28.25 D5.A 58.18,28.25 56.59,29.84 LED1.A
N$35
  Bottom 0.61: K2.9 67.45,20.64 67.44,20.63 65.56,20.63
  Bottom 0.813: 65.56,20.63 63.02,18.09 D6.A 57.86,18.09 56.59,19.36 LED2.A
N$36
  Bottom 0.813: Q4.3 52.78,11.11 LED3.K
N$37
  Bottom 0.61: D7.A 35.65,30.47 36.79,31.62 39.33,31.62 40.73,33.02 LED4.A
  Bottom 0.813: D7.A 35.65,23.36 36.79,22.22 K4.9
N$38
  Bottom 0.61: D8.A 23.96,30.47 24.85,31.36 27.9,31.36 28.92,32.38 28.92,33.4 28.98,33.33 LED5.A
  Bottom 0.813: D8.A 23.96,23.36 25.11,22.22 K5.9 26.63,22.22
N$39
  Bottom 0.813: Q2.3 52.78,31.74 LED1.K
N$40
  Bottom 0.61: Q6.3 27.77,37.14 LED5.K
N$41
  Bottom 0.61: Q5.3 39.46,37.14 LED4.K
N$42  (via drill 0.6 pad 2.54)
  Bottom 0.813: R18.1 92.23,21.9 94.13,23.81 96.67,23.81 98.26,25.39 98.26,76.19 96.36,78.1 v60.48,78.1 47.14,78.1 46.19,77.15 LCD1.15
N$43  (via drill 0.5 pad 1.02)
  Top 0.254: v65.24,40.32 v72.28,40.32
  Bottom 0.813: K1.6 K1.5 63.82,35.85 65.24,37.02 v65.24,40.32 | X1.A10 80.42,51.37 77.3,48.26 77.3,43.49 74.13,40.32 v72.28,40.32
N$44
  Bottom 0.813: K1.10 70.89,30.77 73.48,33.36 73.48,37.47 78.89,42.86 78.89,46.98 80.78,48.87 X1.A9
N$45  (via drill 0.5 pad 1.78)
  other vias: 31.85,13.25
N$46
  Bottom 1.27: 45.87,73.34 48.09,73.34
N$47
  Bottom 0.813: 10,4.12 10,10.47
N$48  (via drill 0.5 pad 1.02, 0.6)
  Top 0.254: v62.74,39.21 v77.44,39.21 | v58.22,25.71 v58.22,31.43
  Bottom 0.813: K2.6 K2.5 v58.22,25.71 | X1.A8 81.45,46.37 80.48,45.4 80.48,42.22 v77.44,39.21 | v62.74,39.21 59.05,39.21 58.22,38.17 v58.22,31.43
N$49
  Bottom 0.813: K2.10 71.14,20.63 72.1,21.58 72.11,29.24 72.15,29.26 74.99,32.06 74.99,34.15 75.01,34.21 75,34.23 | X1.A7 83.4,43.87 82.39,42.86 82.39,41.77 78.12,37.46 76.49,37.46 74.98,36 75,34.23 | 75,34.23 75.01,34.16
N$50  (via drill 0.6)
  Top 0.254: v65.18,16.19 v69.05,16.19
  Bottom 0.813: K3.6 K3.5 63.93,13.98 65.18,15.04 v65.18,16.19 | X1.A6 85.8,41.35 78.26,33.78 78.26,30.16 75.08,26.98 75.08,19.04 72.22,16.19 v69.05,16.19
N$51
  Bottom 0.813: K3.10 73.18,8.89 74.13,9.84 74.13,15.55 76.66,18.09 76.67,26.03 80.25,29.66 80.25,33.5 85.83,39.02 90,39.05 90.05,39.01 X1.A5
N$52
  Bottom 0.813: X1.A4 85.38,36.29 82.03,32.94 82.03,29.17 78.26,25.39 78.26,17.24 75.72,14.6 | 75.72,14.6 75.72,10.47 | 75.72,14.6 75.72,5.62 74.77,4.76 44.6,4.76 43.65,5.71 43.65,16.07 45.34,17.84 45.34,22.77 45.29,22.93 43.27,24.94 43.26,24.94 K4.5 | K4.5 K4.6 | K4.5 43.27,29.89
N$53
  Bottom 0.813: X1.A3 85.42,33.87 83.67,32.06 83.67,28.63 79.84,24.76 79.84,16.5 77.3,13.97 | 77.3,13.97 77.3,11.74 | 77.3,13.97 77.3,4.44 76.35,3.49 43.33,3.49 42.06,4.76 42.06,13.65 39.59,16.12 | 39.59,16.12 39.52,16.19 | K4.10 38.19,17.52 39.59,16.12
N$54  (via drill 0.6)  (1 unrouted)
  Top 0.254: v33.74,20.7 v33.74,26.28
  Bottom 0.813: X1.A2 86.14,31.37 85.43,30.74 85.43,27.86 81.43,23.88 81.43,15.87 78.89,13.33 78.89,3.49 77.62,2.22 42.38,2.22 40.48,4.12 40.48,13.01 38.25,15.24 38.27,15.24 35.62,17.9 34.76,17.9 33.74,18.92 v33.74,20.7 | K5.6 31.27,29.84 | v33.74,26.28 33.74,28.82 32.73,29.84 K5.5
N$55
  Bottom 0.61: 26.5,19.55 26.38,19.43 | 26.5,19.55 K5.10 | 26.63,19.68 26.5,19.55
  Bottom 0.813: X1.A1 88.65,28.87 83.27,23.49 83.27,15.11 80.99,12.82 80.99,3.42 78.45,0.88 41.36,0.88 38.82,3.42 38.82,12.57 34.76,16.63 31.46,16.63 28.41,19.68 26.63,19.68 | K5.10 26.38,19.68
N$56
  Bottom 0.61: LCD1.3 15.71,71.75 14.12,70.16 7.46,70.16 6.18,68.89 6.18,65.08 7.14,64.13 9.69,64.13 12.78,61.07 12.8,57.62 12.79,57.63 13.17,57.2 14.44,56.13 14.44,52.7 13.17,51.43 6.82,51.43 5.55,50.16 5.55,39.37 6.82,38.1 7.77,38.1 8.73,37.14 8.73,34.29 8.09,33.65 R17.2
N$57
  Bottom 0.813: 18.88,4.12 18.88,10.47
N$58
  Bottom 0.813: 27.77,4.12 27.77,10.47
N$59  (via drill 0.6)
  other vias: 60.48,74.92
N$60
  Bottom 1.27: R18.2 96.67,21.9 95.8,21.03 95.8,16.75 S1.3
N$61  (via drill 0.6)
  other vias: 52.73,39.17
N$62  (via drill 0.5 pad 1.78)
  Bottom 0.406: 34.7,13.33 34.67,13.36
  Bottom 0.61: 36.31,10.4 35.5,10.4 34.7,11.2 34.7,13.33
  other vias: 34.7,13.25
N$63
  Bottom 0.254: 61.66,43.48 61.45,43.48
(copper drawn outside any net)
  shapes: Bottom circle x1

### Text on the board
tPlace: Reset | Light | S | 1 | 2 | 3 | +UB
